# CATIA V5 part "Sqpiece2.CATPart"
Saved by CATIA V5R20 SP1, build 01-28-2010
Part number: Sqpiece2
Publications: "Droite.2", "Plan.1", "Droite.3", "Plan.2", "Longueur2", "Droite.1"
Bounding box of the stored display mesh (mm): x 0 to 120, y -20 to 20, z 0 to 0
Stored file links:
  C:\Users\RENARD Simon\Documents\Cours IFMA\2ème année\IAO\Sqpiece2.CATPart
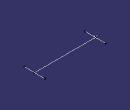
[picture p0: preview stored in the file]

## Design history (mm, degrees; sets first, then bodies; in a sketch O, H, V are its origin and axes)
Parameters
  Longueur2 = 120 mm
Body1 (main body)
  Point1: (0, 0, 0)
  Line1: type PtDir, RefPoint Point1, Direction yz-plane, Start 0, End 120 {= Longueur2}
  Line2: type PtDir, RefPoint vertex of Line1, Direction zx-plane, Start -20, End 20
  Line3: type PtDir, RefPoint Point1, Direction zx-plane, Start -20, End 20
  Plane1: type OffsetPt, RefPlane zx-plane, RefPoint vertex of Line2
  Plane2: type OffsetPt, RefPlane zx-plane, RefPoint vertex of Line3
